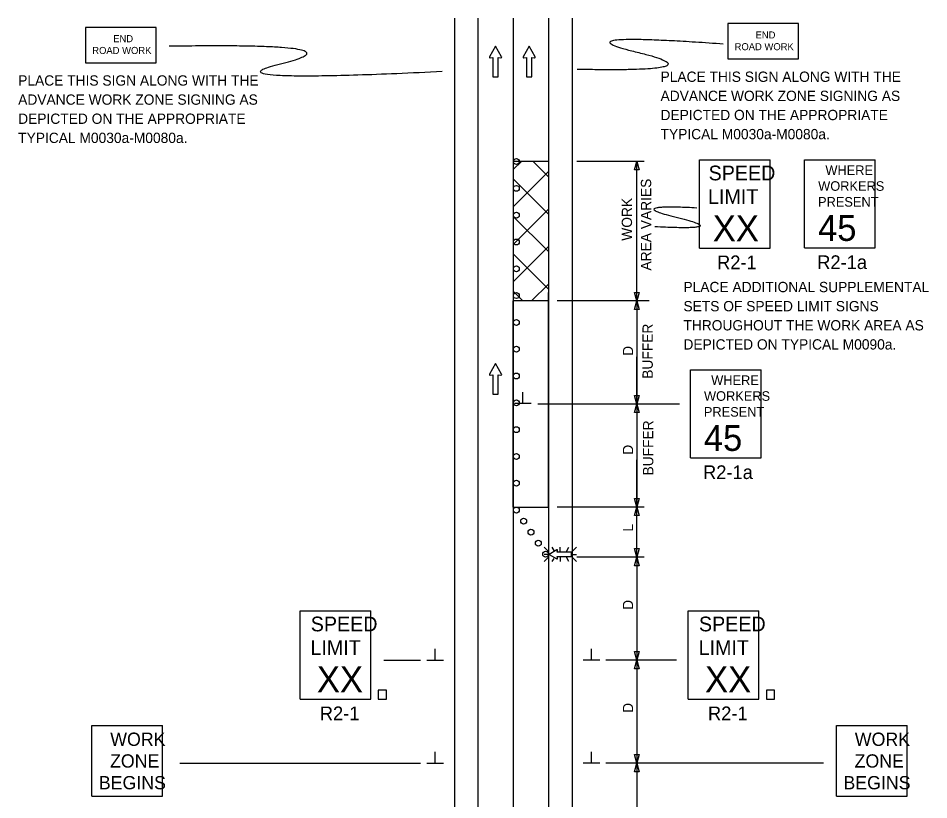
# Model space of a CAD drawing. Extents: x 16739 to 18475, y 5720 to 6924.
# Drawn here: x 16802 to 17421, y 6393 to 6924 of the extents above; entities that cross this region are included whole.
import ezdxf

# ---------------------------------------------------------------- set-up
doc = ezdxf.new("R2010")
doc.units = 0
for name, color, linetype in [('ALI_LEGAL_EX', 7, 'Continuous'), ('MT_SCRATCH_LEVEL_A', 7, 'Continuous'), ('MT_SCRATCH_LEVEL_E', 7, 'Continuous'), ('PAVT_EDGE_EX', 7, 'Continuous'), ('TRAFFIC_SIGNS_PR', 7, 'Continuous'), ('TYPICAL_TEXT_DIMEN_PR', 7, 'Continuous')]:
    doc.layers.add(name, color=color, linetype=linetype)

msp = doc.modelspace()

# ---------------------------------------------------------------- linework, layer by layer
at = {"layer": 'ALI_LEGAL_EX'}
msp.add_line((17138.25, 6923.7), (17138.25, 6094.51), dxfattribs=at)
for points in [[(17138.25, 6923.7), (17138.25, 6898.7)], [(17138.25, 6823.7), (17138.25, 6798.7)], [(17138.25, 6723.7), (17138.25, 6698.7)], [(17138.25, 6623.7), (17138.25, 6598.7)], [(17138.25, 6523.7), (17138.25, 6498.7)], [(17138.25, 6423.7), (17138.25, 6398.7)]]:
    msp.add_lwpolyline(points, dxfattribs=at)
at = {"layer": 'MT_SCRATCH_LEVEL_A'}
for p, q in [((17162.25, 6826.44), (17138.25, 6826.44)), ((17138.25, 6820.88), (17143.81, 6826.44)), ((17162.25, 6815.98), (17151.78, 6826.44)), ((17138.25, 6795.43), (17162.25, 6819.43)), ((17162.25, 6790.52), (17138.25, 6814.52)), ((17138.25, 6769.97), (17162.25, 6793.97)), ((17162.25, 6765.07), (17138.25, 6789.07)), ((17138.25, 6744.52), (17162.25, 6768.52)), ((17162.25, 6739.61), (17138.25, 6763.61)), ((17150.74, 6731.55), (17162.25, 6743.06)), ((17144.86, 6731.55), (17138.25, 6738.15)), ((17162.25, 6623.61), (17162.25, 6737.33)), ((17138.25, 6623.61), (17138.25, 6623.61)), ((17138.25, 6591.55), (17162.25, 6591.55)), ((17138.25, 6591.55), (17162.25, 6591.55))]:
    msp.add_line(p, q, dxfattribs=at)
at = {"layer": 'MT_SCRATCH_LEVEL_E'}
for p, q in [((17126.22, 6904.72), (17122.11, 6897.48)), ((17126.22, 6904.72), (17122.11, 6897.48)), ((17130.37, 6897.48), (17126.22, 6904.72)), ((17130.37, 6897.48), (17126.22, 6904.72)), ((17149.05, 6904.72), (17144.93, 6897.48)), ((17149.05, 6904.72), (17144.93, 6897.48)), ((17153.19, 6897.48), (17149.05, 6904.72)), ((17153.19, 6897.48), (17149.05, 6904.72)), ((17122.59, 6896.79), (17124.37, 6897.11)), ((17122.59, 6896.79), (17124.37, 6897.11)), ((17124.37, 6897.11), (17124.37, 6883.85)), ((17124.37, 6897.11), (17124.37, 6883.85)), ((17128.11, 6883.85), (17128.11, 6897.11)), ((17128.11, 6897.11), (17129.89, 6896.79)), ((17128.11, 6883.85), (17128.11, 6897.11)), ((17128.11, 6897.11), (17129.89, 6896.79)), ((17145.42, 6896.79), (17147.19, 6897.11)), ((17145.42, 6896.79), (17147.19, 6897.11)), ((17147.19, 6897.11), (17147.19, 6883.85)), ((17147.19, 6897.11), (17147.19, 6883.85)), ((17150.94, 6883.85), (17150.94, 6897.11)), ((17150.94, 6897.11), (17152.71, 6896.79)), ((17150.94, 6883.85), (17150.94, 6897.11)), ((17150.94, 6897.11), (17152.71, 6896.79)), ((17124.37, 6883.85), (17128.11, 6883.85)), ((17124.37, 6883.85), (17128.11, 6883.85)), ((17147.19, 6883.85), (17150.94, 6883.85)), ((17147.19, 6883.85), (17150.94, 6883.85)), ((17126.22, 6689), (17122.11, 6681.76)), ((17126.22, 6689), (17122.11, 6681.76)), ((17130.37, 6681.76), (17126.22, 6689)), ((17130.37, 6681.76), (17126.22, 6689)), ((17122.59, 6681.08), (17124.37, 6681.4)), ((17122.59, 6681.08), (17124.37, 6681.4)), ((17124.37, 6681.4), (17124.37, 6668.14)), ((17124.37, 6681.4), (17124.37, 6668.14)), ((17128.11, 6668.14), (17128.11, 6681.4)), ((17128.11, 6681.4), (17129.89, 6681.08)), ((17128.11, 6668.14), (17128.11, 6681.4)), ((17128.11, 6681.4), (17129.89, 6681.08)), ((17124.37, 6668.14), (17128.11, 6668.14)), ((17124.37, 6668.14), (17128.11, 6668.14))]:
    msp.add_line(p, q, dxfattribs=at)
for centre, start, end in [((17122.51, 6897.25), 150.42484, 279.96381), ((17122.51, 6897.25), 150.42484, 279.96381), ((17129.96, 6897.25), 260.03619, 29.77312), ((17129.96, 6897.25), 260.03619, 29.77312), ((17145.34, 6897.25), 150.42484, 279.96381), ((17145.34, 6897.25), 150.42484, 279.96381), ((17152.78, 6897.25), 260.03619, 29.77312), ((17152.78, 6897.25), 260.03619, 29.77312), ((17122.51, 6681.54), 150.42484, 279.96381), ((17122.51, 6681.54), 150.42484, 279.96381), ((17129.96, 6681.54), 260.03619, 29.77312), ((17129.96, 6681.54), 260.03619, 29.77312)]:
    msp.add_arc(centre, 0.463, start, end, dxfattribs=at)
at = {"layer": 'PAVT_EDGE_EX'}
for p, q in [((17098.25, 6923.7), (17098.25, 6094.51)), ((17114.25, 6923.7), (17114.25, 6094.51)), ((17162.25, 6923.7), (17162.25, 6094.51)), ((17178.25, 6923.7), (17178.25, 6094.51))]:
    msp.add_line(p, q, dxfattribs=at)
msp.add_lwpolyline([(17162.08, 6731.55), (17137.87, 6731.55), (17137.87, 6591.55), (17162.08, 6591.55)], close=True, dxfattribs=at)
at = {"layer": 'TRAFFIC_SIGNS_PR'}
for p, q in [((17264.67, 6827.46), (17312.67, 6827.46)), ((17264.67, 6767.46), (17264.67, 6827.46)), ((17312.67, 6767.46), (17312.67, 6827.46)), ((17336.17, 6827.57), (17384.17, 6827.57)), ((17336.17, 6767.57), (17336.17, 6827.57)), ((17384.17, 6767.57), (17384.17, 6827.57)), ((17264.67, 6767.46), (17312.67, 6767.46)), ((17336.17, 6767.57), (17384.17, 6767.57)), ((17258.59, 6684.87), (17306.59, 6684.87)), ((17258.59, 6624.87), (17258.59, 6684.87)), ((17306.59, 6624.87), (17306.59, 6684.87)), ((17258.59, 6624.87), (17306.59, 6624.87)), ((17159.29, 6564.26), (17162.11, 6561.44)), ((17166.01, 6562.08), (17164.75, 6564.26)), ((17170.2, 6561.44), (17170.2, 6564.26)), ((17174.33, 6561.44), (17175.96, 6564.26)), ((17178.28, 6561.44), (17181.1, 6564.27)), ((17162.11, 6559.41), (17159.29, 6559.41)), ((17159.29, 6554.56), (17162.11, 6557.38)), ((17170.2, 6557.38), (17170.2, 6554.56)), ((17175.99, 6554.56), (17174.36, 6557.38)), ((17178.28, 6559.41), (17181.1, 6559.41)), ((17178.28, 6557.38), (17181.1, 6554.56)), ((17164.73, 6554.56), (17165.94, 6556.65)), ((16993.48, 6521), (17041.48, 6521)), ((16993.48, 6461), (16993.48, 6521)), ((17041.48, 6461), (17041.48, 6521)), ((17257.18, 6521), (17305.18, 6521)), ((17257.18, 6461), (17257.18, 6521)), ((17305.18, 6461), (17305.18, 6521)), ((16993.48, 6461), (17041.48, 6461)), ((17257.18, 6461), (17305.18, 6461)), ((16851.97, 6395.06), (16851.97, 6443.06)), ((16851.97, 6443.06), (16899.97, 6443.06)), ((16899.97, 6395.06), (16899.97, 6443.06)), ((17357.78, 6395.06), (17357.78, 6443.06)), ((17357.78, 6443.06), (17405.78, 6443.06)), ((17405.78, 6395.06), (17405.78, 6443.06)), ((16851.97, 6395.06), (16899.97, 6395.06)), ((17357.78, 6395.06), (17405.78, 6395.06))]:
    msp.add_line(p, q, dxfattribs=at)
for points in [[(16847.73, 6893.48), (16895.73, 6893.48), (16895.73, 6917.48), (16847.73, 6917.48)], [(17284.1, 6896.02), (17332.1, 6896.02), (17332.1, 6920.02), (17284.1, 6920.02)], [(17046.49, 6461), (17052.09, 6461), (17052.09, 6467.17), (17046.49, 6467.17)], [(17310.19, 6461), (17315.79, 6461), (17315.79, 6467.17), (17310.19, 6467.17)]]:
    msp.add_lwpolyline(points, close=True, dxfattribs=at)
for points in [[(17167.87, 6562.43), (17162.56, 6559.41), (17167.87, 6556.37)], [(17168.37, 6556.73), (17168.14, 6558.03), (17177.86, 6558.03), (17177.86, 6560.77), (17168.14, 6560.77), (17168.37, 6562.07)]]:
    msp.add_lwpolyline(points, dxfattribs=at)
for centre in [(17140.35, 6826.28), (17140.35, 6808.07), (17140.35, 6789.85), (17140.35, 6771.64), (17140.35, 6753.42), (17140.35, 6735.21), (17140.35, 6716.99), (17140.35, 6698.78), (17140.35, 6680.57), (17140.35, 6662.35), (17140.35, 6644.14), (17140.35, 6625.92), (17140.35, 6607.71), (17140.35, 6589.49), (17145.32, 6581.98), (17150.29, 6574.48), (17155.26, 6566.98), (17160.23, 6559.47)]:
    msp.add_circle(centre, 2, dxfattribs=at)
for centre, start, end in [((17168.04, 6562.13), 350.73078, 118.89165), ((17168.03, 6556.67), 241.48329, 9.95933)]:
    msp.add_arc(centre, 0.341, start, end, dxfattribs=at)
for points in [[(17090.03, 6887.43), (16924.1, 6879.19), (17038.01, 6906.77), (16904.59, 6904.61)], [(17280.9, 6906.12), (17165.67, 6914.35), (17279.58, 6886.77), (17181.64, 6888.94)], [(17262.93, 6794.73), (17212.35, 6797.32), (17287.09, 6779.23), (17234.5, 6781.96)]]:
    msp.add_open_spline(points, degree=2, dxfattribs=at)
at = {"layer": 'TYPICAL_TEXT_DIMEN_PR'}
for p, q in [((17227.25, 6826.44), (17181.55, 6826.44)), ((17220.68, 6820.58), (17222.25, 6826.44)), ((17222.25, 6731.55), (17222.25, 6826.44)), ((17222.25, 6826.44), (17223.82, 6820.58)), ((17222.25, 6820.58), (17220.68, 6820.58)), ((17223.82, 6820.58), (17222.25, 6820.58)), ((17222.25, 6731.55), (17220.68, 6737.41)), ((17220.68, 6737.41), (17222.25, 6737.41)), ((17222.25, 6737.41), (17223.82, 6737.41)), ((17223.82, 6737.41), (17222.25, 6731.55)), ((17230.61, 6731.55), (17168.14, 6731.55)), ((17220.68, 6725.69), (17222.25, 6731.55)), ((17222.25, 6731.55), (17223.82, 6725.69)), ((17222.25, 6731.55), (17222.25, 6661.55)), ((17222.25, 6725.69), (17220.68, 6725.69)), ((17223.82, 6725.69), (17222.25, 6725.69)), ((17222.25, 6661.55), (17222.25, 6693.61)), ((17144.71, 6661.9), (17144.71, 6669.68)), ((17222.25, 6661.55), (17220.68, 6667.41)), ((17220.68, 6667.41), (17222.25, 6667.41)), ((17222.25, 6667.41), (17223.82, 6667.41)), ((17223.82, 6667.41), (17222.25, 6661.55)), ((17150.34, 6661.9), (17139.09, 6661.9)), ((17251.21, 6661.55), (17155, 6661.55)), ((17220.68, 6655.69), (17222.25, 6661.55)), ((17222.25, 6661.55), (17223.82, 6655.69)), ((17222.25, 6661.55), (17222.25, 6591.55)), ((17222.25, 6655.69), (17220.68, 6655.69)), ((17223.82, 6655.69), (17222.25, 6655.69)), ((17222.25, 6591.55), (17222.25, 6623.61)), ((17222.25, 6591.55), (17220.68, 6597.41)), ((17220.68, 6597.41), (17222.25, 6597.41)), ((17222.25, 6597.41), (17223.82, 6597.41)), ((17223.82, 6597.41), (17222.25, 6591.55)), ((17227.25, 6591.55), (17168.14, 6591.55)), ((17220.68, 6585.69), (17222.25, 6591.55)), ((17222.25, 6557.44), (17222.25, 6591.55)), ((17222.25, 6591.55), (17223.82, 6585.69)), ((17222.25, 6585.69), (17220.68, 6585.69)), ((17223.82, 6585.69), (17222.25, 6585.69)), ((17222.25, 6557.44), (17220.68, 6563.3)), ((17220.68, 6563.3), (17222.25, 6563.3)), ((17222.25, 6563.3), (17223.82, 6563.3)), ((17223.82, 6563.3), (17222.25, 6557.44)), ((17227.25, 6557.44), (17181.55, 6557.44)), ((17220.68, 6551.57), (17222.25, 6557.44)), ((17222.25, 6557.44), (17222.25, 6487.44)), ((17222.25, 6557.44), (17223.82, 6551.57)), ((17222.25, 6551.57), (17220.68, 6551.57)), ((17223.82, 6551.57), (17222.25, 6551.57)), ((17222.25, 6512.31), (17222.25, 6508.54)), ((17085.12, 6487.44), (17085.12, 6495.22)), ((17191.38, 6487.44), (17191.38, 6495.22)), ((17222.25, 6487.44), (17220.68, 6493.3)), ((17220.68, 6493.3), (17222.25, 6493.3)), ((17222.25, 6493.3), (17223.82, 6493.3)), ((17223.82, 6493.3), (17222.25, 6487.44)), ((17050.31, 6487.44), (17075.25, 6487.44)), ((17079.5, 6487.44), (17090.75, 6487.44)), ((17197, 6487.44), (17185.75, 6487.44)), ((17249.19, 6487.44), (17201.25, 6487.44)), ((17220.68, 6481.57), (17222.25, 6487.44)), ((17222.25, 6487.44), (17222.25, 6417.44)), ((17222.25, 6487.44), (17223.82, 6481.57)), ((17222.25, 6481.57), (17220.68, 6481.57)), ((17223.82, 6481.57), (17222.25, 6481.57)), ((17085.12, 6417.44), (17085.12, 6425.22)), ((17191.38, 6417.44), (17191.38, 6425.22)), ((17222.25, 6417.44), (17220.68, 6423.3)), ((17220.68, 6423.3), (17222.25, 6423.3)), ((17222.25, 6423.3), (17223.82, 6423.3)), ((17223.82, 6423.3), (17222.25, 6417.44)), ((16911.66, 6417.44), (17075.25, 6417.44)), ((17079.5, 6417.44), (17090.75, 6417.44)), ((17197, 6417.44), (17185.75, 6417.44)), ((17348.94, 6417.44), (17201.25, 6417.44)), ((17220.68, 6411.57), (17222.25, 6417.44)), ((17222.25, 6417.44), (17223.82, 6411.57)), ((17222.25, 6417.44), (17222.25, 6347.44)), ((17222.25, 6411.57), (17220.68, 6411.57)), ((17223.82, 6411.57), (17222.25, 6411.57))]:
    msp.add_line(p, q, dxfattribs=at)

# ---------------------------------------------------------------- texts
at = {"layer": 'TRAFFIC_SIGNS_PR'}
for s, height, p in [('END', 4.789, (16866.49, 6907.39)), ('END', 4.789, (17302.85, 6909.93)), ('ROAD WORK', 4.789, (16852.25, 6899.41)), ('ROAD WORK', 4.789, (17288.61, 6901.95)), ('PLACE THIS SIGN ALONG WITH THE', 7, (16801.93, 6877.9)), ('PLACE THIS SIGN ALONG WITH THE', 7, (17238.3, 6880.44)), ('ADVANCE WORK ZONE SIGNING AS', 7, (17238.3, 6867.44)), ('ADVANCE WORK ZONE SIGNING AS', 7, (16801.93, 6864.9)), ('DEPICTED ON THE APPROPRIATE', 7, (17238.3, 6854.44)), ('DEPICTED ON THE APPROPRIATE', 7, (16801.93, 6851.9)), ('TYPICAL M0030a-M0080a.', 7, (17238.3, 6841.44)), ('TYPICAL M0030a-M0080a.', 7, (16801.93, 6838.9)), ('SPEED', 10, (17270.96, 6813.53)), ('WHERE', 6.5, (17350.3, 6817.17)), ('WORKERS', 6.5, (17345.4, 6806.42)), ('LIMIT', 10, (17270.55, 6797.53)), ('PRESENT', 6.5, (17345.31, 6795.67)), ('XX', 17.538, (17273.81, 6772.15)), ('45', 17.538, (17345.3, 6772.38)), ('R2-1', 9.3, (17276.68, 6753.16)), ('R2-1a', 9.3, (17344.73, 6753.27)), ('PLACE ADDITIONAL SUPPLEMENTAL', 7, (17253.86, 6737.55)), ('SETS OF SPEED LIMIT SIGNS', 7, (17253.86, 6724.55)), ('THROUGHOUT THE WORK AREA AS', 7, (17253.86, 6711.55)), ('DEPICTED ON TYPICAL M0090a.', 7, (17253.86, 6698.55)), ('WHERE', 6.5, (17272.73, 6674.48)), ('WORKERS', 6.5, (17267.82, 6663.73)), ('PRESENT', 6.5, (17267.74, 6652.98)), ('45', 17.538, (17267.72, 6629.69)), ('R2-1a', 9.3, (17267.16, 6610.57)), ('SPEED', 10, (17000.69, 6507.08)), ('SPEED', 10, (17264.39, 6507.08)), ('LIMIT', 10, (17000.48, 6491.08)), ('LIMIT', 10, (17264.18, 6491.08)), ('XX', 17.538, (17004.87, 6465.7)), ('XX', 17.538, (17268.57, 6465.7)), ('R2-1', 9.3, (17006.82, 6446.7)), ('R2-1', 9.3, (17270.52, 6446.7)), ('WORK', 9.021, (16864.47, 6429.26)), ('WORK', 9.021, (17370.28, 6429.26)), ('ZONE', 9.021, (16864.32, 6414.5)), ('ZONE', 9.021, (17370.13, 6414.5)), ('BEGINS', 9.021, (16856.73, 6399.74)), ('BEGINS', 9.021, (17362.54, 6399.74))]:
    msp.add_text(s, height=height, dxfattribs=at).set_placement(p)
at = {"layer": 'TYPICAL_TEXT_DIMEN_PR'}
for s, p in [('AREA VARIES', (17231.94, 6752.25)), ('WORK', (17218.94, 6772.49)), ('BUFFER', (17233.03, 6678.71)), ('D', (17219.69, 6694.24)), ('BUFFER', (17233.39, 6612.99)), ('D', (17219.69, 6627.1)), ('L', (17219.69, 6574.84)), ('D', (17219.69, 6521.66)), ('D', (17219.69, 6451.66))]:
    msp.add_text(s, height=7, rotation=90, dxfattribs=at).set_placement(p)

doc.saveas('drawing.dxf')
